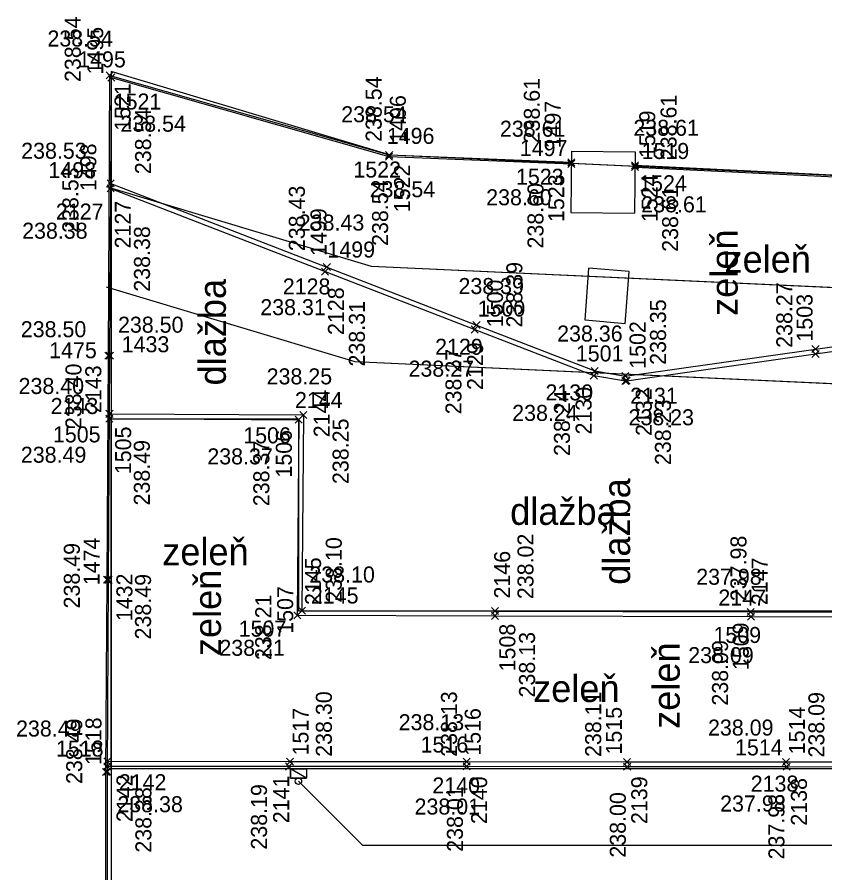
# Model space of a CAD drawing. Extents: x -264205 to -263659, y -1242401 to -1241986.
# Drawn here: x -263962.4 to -263937.18, y -1242084.56 to -1242057.84 of the extents above; entities that cross this region are included whole.
import ezdxf

# ---------------------------------------------------------------- set-up
doc = ezdxf.new("R2010")
doc.units = 0
for name, color, linetype in [('BOD_CISLO_2-2', 7, 'Continuous'), ('BOD_CISLO_2-3', 7, 'Continuous'), ('BOD_SYMBOL_2-2', 7, 'Continuous'), ('BOD_SYMBOL_2-3', 7, 'Continuous'), ('BOD_VYSKA_2-2', 7, 'Continuous'), ('BOD_VYSKA_2-3', 7, 'Continuous'), ('KFA_JESTVUJUCE_SACHTY', 7, 'Continuous'), ('POPIS_2-2', 7, 'Continuous'), ('POPIS_2-3', 7, 'Continuous'), ('PROJEKT_OBRUBNIKY_KOMUNIKACIE', 7, 'Continuous'), ('SITUACIA_DSP_2D', 7, 'Continuous'), ('SO_20-4_OBRUBNIKY_DOLNA_HRANA', 7, 'Continuous'), ('SO_20-4_OBRUBNIKY_HORNA_HRANA', 7, 'Continuous')]:
    doc.layers.add(name, color=color, linetype=linetype)

msp = doc.modelspace()

# ---------------------------------------------------------------- linework, layer by layer
at = {"layer": 'BOD_SYMBOL_2-2'}
for p, q in [((-263959.62, -1242059.771), (-263959.399, -1242059.549)), ((-263959.399, -1242059.771), (-263959.62, -1242059.549)), ((-263959.569, -1242059.836), (-263959.349, -1242059.616)), ((-263959.349, -1242059.836), (-263959.569, -1242059.616)), ((-263950.903, -1242062.306), (-263950.682, -1242062.085)), ((-263950.682, -1242062.306), (-263950.903, -1242062.085)), ((-263950.894, -1242062.255), (-263950.674, -1242062.035)), ((-263950.674, -1242062.255), (-263950.894, -1242062.035)), ((-263945.205, -1242062.482), (-263944.985, -1242062.262)), ((-263944.985, -1242062.482), (-263945.205, -1242062.262)), ((-263945.205, -1242062.532), (-263944.985, -1242062.312)), ((-263944.985, -1242062.532), (-263945.205, -1242062.312)), ((-263943.215, -1242062.579), (-263942.995, -1242062.357)), ((-263942.995, -1242062.579), (-263943.215, -1242062.357)), ((-263943.215, -1242062.633), (-263942.995, -1242062.413)), ((-263942.995, -1242062.633), (-263943.215, -1242062.413)), ((-263959.588, -1242063.144), (-263959.367, -1242062.924)), ((-263959.367, -1242063.144), (-263959.588, -1242062.924)), ((-263959.589, -1242063.299), (-263959.367, -1242063.079)), ((-263959.367, -1242063.299), (-263959.589, -1242063.079)), ((-263952.895, -1242065.894), (-263952.675, -1242065.674)), ((-263952.675, -1242065.894), (-263952.895, -1242065.674)), ((-263952.84, -1242065.755), (-263952.618, -1242065.535)), ((-263952.618, -1242065.755), (-263952.84, -1242065.535)), ((-263948.22, -1242067.704), (-263948, -1242067.482)), ((-263948, -1242067.704), (-263948.22, -1242067.482)), ((-263948.167, -1242067.568), (-263947.947, -1242067.346)), ((-263947.947, -1242067.568), (-263948.167, -1242067.346)), ((-263959.664, -1242068.525), (-263959.443, -1242068.303)), ((-263959.443, -1242068.525), (-263959.664, -1242068.303)), ((-263959.617, -1242068.525), (-263959.395, -1242068.303)), ((-263959.395, -1242068.525), (-263959.617, -1242068.303)), ((-263937.583, -1242068.465), (-263937.361, -1242068.245)), ((-263937.361, -1242068.465), (-263937.583, -1242068.245)), ((-263937.582, -1242068.316), (-263937.361, -1242068.096)), ((-263937.361, -1242068.316), (-263937.582, -1242068.096)), ((-263944.476, -1242068.998), (-263944.256, -1242068.776)), ((-263944.256, -1242068.998), (-263944.476, -1242068.776)), ((-263944.503, -1242069.144), (-263944.283, -1242068.923)), ((-263944.283, -1242069.144), (-263944.503, -1242068.923)), ((-263943.52, -1242069.16), (-263943.3, -1242068.94)), ((-263943.3, -1242069.16), (-263943.52, -1242068.94)), ((-263943.518, -1242069.309), (-263943.296, -1242069.088)), ((-263943.296, -1242069.309), (-263943.518, -1242069.088)), ((-263943.481, -1242069.306), (-263943.261, -1242069.085)), ((-263943.261, -1242069.306), (-263943.481, -1242069.085)), ((-263959.628, -1242070.339), (-263959.406, -1242070.117)), ((-263959.406, -1242070.339), (-263959.628, -1242070.117)), ((-263953.573, -1242070.372), (-263953.351, -1242070.15)), ((-263953.351, -1242070.372), (-263953.573, -1242070.15)), ((-263959.628, -1242070.488), (-263959.408, -1242070.266)), ((-263959.408, -1242070.488), (-263959.628, -1242070.266)), ((-263953.72, -1242070.521), (-263953.498, -1242070.299)), ((-263953.498, -1242070.521), (-263953.72, -1242070.299)), ((-263959.704, -1242075.516), (-263959.484, -1242075.296)), ((-263959.484, -1242075.516), (-263959.704, -1242075.296)), ((-263959.659, -1242075.521), (-263959.438, -1242075.299)), ((-263959.438, -1242075.521), (-263959.659, -1242075.299)), ((-263953.62, -1242076.478), (-263953.399, -1242076.258)), ((-263953.399, -1242076.478), (-263953.62, -1242076.258)), ((-263947.59, -1242076.494), (-263947.37, -1242076.272)), ((-263947.37, -1242076.494), (-263947.59, -1242076.272)), ((-263939.603, -1242076.522), (-263939.382, -1242076.302)), ((-263939.382, -1242076.522), (-263939.603, -1242076.302)), ((-263953.764, -1242076.626), (-263953.542, -1242076.404)), ((-263953.542, -1242076.626), (-263953.764, -1242076.404)), ((-263947.59, -1242076.644), (-263947.368, -1242076.424)), ((-263947.368, -1242076.644), (-263947.59, -1242076.424)), ((-263939.593, -1242076.668), (-263939.372, -1242076.448)), ((-263939.372, -1242076.668), (-263939.593, -1242076.448)), ((-263959.692, -1242081.343), (-263959.47, -1242081.123)), ((-263959.47, -1242081.343), (-263959.692, -1242081.123)), ((-263959.691, -1242081.194), (-263959.47, -1242080.972)), ((-263959.47, -1242081.194), (-263959.691, -1242080.972)), ((-263954.023, -1242081.349), (-263953.802, -1242081.127)), ((-263953.802, -1242081.349), (-263954.023, -1242081.127)), ((-263953.991, -1242081.201), (-263953.769, -1242080.981)), ((-263953.769, -1242081.201), (-263953.991, -1242080.981)), ((-263948.474, -1242081.2), (-263948.253, -1242080.978)), ((-263948.253, -1242081.2), (-263948.474, -1242080.978)), ((-263948.471, -1242081.345), (-263948.251, -1242081.123)), ((-263948.251, -1242081.345), (-263948.471, -1242081.123)), ((-263943.471, -1242081.208), (-263943.251, -1242080.988)), ((-263943.251, -1242081.208), (-263943.471, -1242080.988)), ((-263943.463, -1242081.353), (-263943.242, -1242081.133)), ((-263943.242, -1242081.353), (-263943.463, -1242081.133)), ((-263938.503, -1242081.211), (-263938.281, -1242080.99)), ((-263938.281, -1242081.211), (-263938.503, -1242080.99)), ((-263938.485, -1242081.357), (-263938.264, -1242081.137)), ((-263938.264, -1242081.357), (-263938.485, -1242081.137)), ((-263959.737, -1242081.516), (-263959.517, -1242081.296)), ((-263959.517, -1242081.516), (-263959.737, -1242081.296)), ((-263959.693, -1242081.512), (-263959.471, -1242081.292)), ((-263959.471, -1242081.512), (-263959.693, -1242081.292))]:
    msp.add_line(p, q, dxfattribs=at)
at = {"layer": 'BOD_SYMBOL_2-3'}
for p, q in [((-263959.399, -1242059.771), (-263959.62, -1242059.549)), ((-263959.399, -1242059.549), (-263959.62, -1242059.771)), ((-263959.349, -1242059.836), (-263959.569, -1242059.616)), ((-263959.349, -1242059.616), (-263959.569, -1242059.836)), ((-263950.682, -1242062.306), (-263950.903, -1242062.085)), ((-263950.682, -1242062.085), (-263950.903, -1242062.306)), ((-263950.674, -1242062.255), (-263950.894, -1242062.035)), ((-263950.674, -1242062.035), (-263950.894, -1242062.255)), ((-263944.985, -1242062.482), (-263945.205, -1242062.262)), ((-263944.985, -1242062.262), (-263945.205, -1242062.482)), ((-263944.985, -1242062.532), (-263945.205, -1242062.312)), ((-263944.985, -1242062.312), (-263945.205, -1242062.532)), ((-263942.995, -1242062.579), (-263943.215, -1242062.357)), ((-263942.995, -1242062.357), (-263943.215, -1242062.579)), ((-263942.995, -1242062.633), (-263943.215, -1242062.413)), ((-263942.995, -1242062.413), (-263943.215, -1242062.633)), ((-263959.367, -1242063.144), (-263959.588, -1242062.924)), ((-263959.367, -1242062.924), (-263959.588, -1242063.144)), ((-263959.367, -1242063.299), (-263959.589, -1242063.079)), ((-263959.367, -1242063.079), (-263959.589, -1242063.299)), ((-263952.675, -1242065.894), (-263952.895, -1242065.674)), ((-263952.675, -1242065.674), (-263952.895, -1242065.894)), ((-263952.618, -1242065.755), (-263952.84, -1242065.535)), ((-263952.618, -1242065.535), (-263952.84, -1242065.755)), ((-263948, -1242067.704), (-263948.22, -1242067.482)), ((-263948, -1242067.482), (-263948.22, -1242067.704)), ((-263947.947, -1242067.568), (-263948.167, -1242067.346)), ((-263947.947, -1242067.346), (-263948.167, -1242067.568)), ((-263959.443, -1242068.525), (-263959.664, -1242068.303)), ((-263959.443, -1242068.303), (-263959.664, -1242068.525)), ((-263959.395, -1242068.525), (-263959.617, -1242068.303)), ((-263959.395, -1242068.303), (-263959.617, -1242068.525)), ((-263937.361, -1242068.465), (-263937.583, -1242068.245)), ((-263937.361, -1242068.245), (-263937.583, -1242068.465)), ((-263937.361, -1242068.316), (-263937.582, -1242068.096)), ((-263937.361, -1242068.096), (-263937.582, -1242068.316)), ((-263944.256, -1242068.998), (-263944.476, -1242068.776)), ((-263944.256, -1242068.776), (-263944.476, -1242068.998)), ((-263944.283, -1242069.144), (-263944.503, -1242068.923)), ((-263944.283, -1242068.923), (-263944.503, -1242069.144)), ((-263943.3, -1242069.16), (-263943.52, -1242068.94)), ((-263943.3, -1242068.94), (-263943.52, -1242069.16)), ((-263943.296, -1242069.309), (-263943.518, -1242069.088)), ((-263943.296, -1242069.088), (-263943.518, -1242069.309)), ((-263943.261, -1242069.306), (-263943.481, -1242069.085)), ((-263943.261, -1242069.085), (-263943.481, -1242069.306)), ((-263959.406, -1242070.339), (-263959.628, -1242070.117)), ((-263959.406, -1242070.117), (-263959.628, -1242070.339)), ((-263953.351, -1242070.372), (-263953.573, -1242070.15)), ((-263953.351, -1242070.15), (-263953.573, -1242070.372)), ((-263959.408, -1242070.488), (-263959.628, -1242070.266)), ((-263959.408, -1242070.266), (-263959.628, -1242070.488)), ((-263953.498, -1242070.521), (-263953.72, -1242070.299)), ((-263953.498, -1242070.299), (-263953.72, -1242070.521)), ((-263959.484, -1242075.516), (-263959.704, -1242075.296)), ((-263959.484, -1242075.296), (-263959.704, -1242075.516)), ((-263959.438, -1242075.521), (-263959.659, -1242075.299)), ((-263959.438, -1242075.299), (-263959.659, -1242075.521)), ((-263953.399, -1242076.478), (-263953.62, -1242076.258)), ((-263953.399, -1242076.258), (-263953.62, -1242076.478)), ((-263947.37, -1242076.494), (-263947.59, -1242076.272)), ((-263947.37, -1242076.272), (-263947.59, -1242076.494)), ((-263939.382, -1242076.522), (-263939.603, -1242076.302)), ((-263939.382, -1242076.302), (-263939.603, -1242076.522)), ((-263953.542, -1242076.626), (-263953.764, -1242076.404)), ((-263953.542, -1242076.404), (-263953.764, -1242076.626)), ((-263947.368, -1242076.644), (-263947.59, -1242076.424)), ((-263947.368, -1242076.424), (-263947.59, -1242076.644)), ((-263939.372, -1242076.668), (-263939.593, -1242076.448)), ((-263939.372, -1242076.448), (-263939.593, -1242076.668)), ((-263959.47, -1242081.343), (-263959.692, -1242081.123)), ((-263959.47, -1242081.123), (-263959.692, -1242081.343)), ((-263959.47, -1242081.194), (-263959.691, -1242080.972)), ((-263959.47, -1242080.972), (-263959.691, -1242081.194)), ((-263953.802, -1242081.349), (-263954.023, -1242081.127)), ((-263953.802, -1242081.127), (-263954.023, -1242081.349)), ((-263953.769, -1242081.201), (-263953.991, -1242080.981)), ((-263953.769, -1242080.981), (-263953.991, -1242081.201)), ((-263948.253, -1242081.2), (-263948.474, -1242080.978)), ((-263948.253, -1242080.978), (-263948.474, -1242081.2)), ((-263948.251, -1242081.345), (-263948.471, -1242081.123)), ((-263948.251, -1242081.123), (-263948.471, -1242081.345)), ((-263943.251, -1242081.208), (-263943.471, -1242080.988)), ((-263943.251, -1242080.988), (-263943.471, -1242081.208)), ((-263943.242, -1242081.353), (-263943.463, -1242081.133)), ((-263943.242, -1242081.133), (-263943.463, -1242081.353)), ((-263938.281, -1242081.211), (-263938.503, -1242080.99)), ((-263938.281, -1242080.99), (-263938.503, -1242081.211)), ((-263938.264, -1242081.357), (-263938.485, -1242081.137)), ((-263938.264, -1242081.137), (-263938.485, -1242081.357)), ((-263959.517, -1242081.516), (-263959.737, -1242081.296)), ((-263959.517, -1242081.296), (-263959.737, -1242081.516)), ((-263959.471, -1242081.512), (-263959.693, -1242081.292)), ((-263959.471, -1242081.292), (-263959.693, -1242081.512))]:
    msp.add_line(p, q, dxfattribs=at)
at = {"layer": 'KFA_JESTVUJUCE_SACHTY'}
for p, q in [((-263945.09, -1242062.026), (-263945.116, -1242063.94)), ((-263944.666, -1242067.305), (-263944.545, -1242065.681))]:
    msp.add_line(p, q, dxfattribs=at)
for points in [[(-263945.09, -1242062.026), (-263943.099, -1242062.048), (-263943.125, -1242063.962)], [(-263945.116, -1242063.94), (-263943.125, -1242063.962)], [(-263943.411, -1242067.412), (-263943.29, -1242065.788), (-263944.545, -1242065.681)], [(-263943.411, -1242067.412), (-263944.666, -1242067.305)]]:
    msp.add_lwpolyline(points, dxfattribs=at)
at = {"layer": 'PROJEKT_OBRUBNIKY_KOMUNIKACIE'}
for p, q in [((-263950.745, -1242062.149), (-263959.468, -1242059.534)), ((-263959.468, -1242059.534), (-263959.468, -1242179.482)), ((-263926.771, -1242063.254), (-263950.745, -1242062.149)), ((-263959.468, -1242071.382), (-263959.468, -1242070.382)), ((-263959.468, -1242070.382), (-263953.617, -1242070.382)), ((-263953.617, -1242070.382), (-263953.617, -1242076.382)), ((-263959.468, -1242076.382), (-263959.468, -1242071.382)), ((-263959.468, -1242081.307), (-263959.468, -1242076.382)), ((-263953.617, -1242076.382), (-263929.58, -1242076.382)), ((-263953.617, -1242081.307), (-263959.468, -1242081.307)), ((-263929.58, -1242081.307), (-263953.617, -1242081.307))]:
    msp.add_line(p, q, dxfattribs=at)
for points in [[(-263863.949, -1242065.106), (-263895.455, -1242062.322), (-263915.197, -1242060.921), (-263926.771, -1242063.254), (-263950.745, -1242062.149), (-263959.468, -1242059.534)], [(-263864.257, -1242068.593), (-263895.733, -1242065.811), (-263914.971, -1242064.445), (-263926.501, -1242066.77), (-263951.337, -1242065.625), (-263959.611, -1242063.145)], [(-263864.521, -1242071.581), (-263895.971, -1242068.802), (-263914.777, -1242067.467), (-263926.271, -1242069.784), (-263951.845, -1242068.605), (-263959.611, -1242066.277)]]:
    msp.add_lwpolyline(points, dxfattribs=at)
at = {"layer": 'SITUACIA_DSP_2D'}
for p, q in [((-263959.468, -1242059.534), (-263959.468, -1242179.482)), ((-263950.745, -1242062.149), (-263959.468, -1242059.534)), ((-263950.745, -1242062.149), (-263959.468, -1242059.534)), ((-263926.771, -1242063.254), (-263950.745, -1242062.149)), ((-263926.771, -1242063.254), (-263950.745, -1242062.149)), ((-263951.337, -1242065.625), (-263959.611, -1242063.145)), ((-263926.501, -1242066.77), (-263951.337, -1242065.625)), ((-263951.845, -1242068.605), (-263959.611, -1242066.277)), ((-263926.271, -1242069.784), (-263951.845, -1242068.605)), ((-263959.468, -1242071.382), (-263959.468, -1242070.382)), ((-263959.468, -1242070.382), (-263953.617, -1242070.382)), ((-263953.617, -1242070.382), (-263953.617, -1242076.382)), ((-263959.468, -1242076.382), (-263959.468, -1242071.382)), ((-263959.468, -1242081.307), (-263959.468, -1242076.382)), ((-263953.617, -1242076.382), (-263929.58, -1242076.382)), ((-263953.617, -1242081.307), (-263959.468, -1242081.307)), ((-263953.868, -1242081.597), (-263953.868, -1242081.307)), ((-263953.868, -1242081.307), (-263953.368, -1242081.307)), ((-263953.368, -1242081.597), (-263953.868, -1242081.307)), ((-263953.368, -1242081.597), (-263953.868, -1242081.307)), ((-263953.868, -1242081.307), (-263953.868, -1242081.597)), ((-263929.58, -1242081.307), (-263953.617, -1242081.307)), ((-263953.368, -1242081.307), (-263953.368, -1242081.597)), ((-263953.368, -1242081.597), (-263953.868, -1242081.597)), ((-263953.868, -1242081.597), (-263953.368, -1242081.597)), ((-263953.618, -1242081.697), (-263951.618, -1242083.697)), ((-263953.547, -1242081.768), (-263951.618, -1242083.697)), ((-263951.618, -1242083.697), (-263918.806, -1242083.697))]:
    msp.add_line(p, q, dxfattribs=at)
msp.add_circle((-263953.618, -1242081.697), 0.1, dxfattribs=at)
at = {"layer": 'SO_20-4_OBRUBNIKY_DOLNA_HRANA'}
msp.add_line((-263959.517, -1242070.228), (-263953.462, -1242070.261), dxfattribs=at)
for points in [[(-263959.478, -1242063.189), (-263952.785, -1242065.784), (-263948.11, -1242067.593), (-263944.393, -1242069.033), (-263943.407, -1242069.198), (-263943.371, -1242069.195), (-263937.472, -1242068.355), (-263932.521, -1242067.649), (-263926.563, -1242066.793)], [(-263953.462, -1242070.261), (-263953.509, -1242076.368), (-263947.48, -1242076.383), (-263939.492, -1242076.412), (-263933.989, -1242076.423), (-263929.589, -1242076.427)], [(-263929.589, -1242076.427), (-263929.578, -1242081.252), (-263933.379, -1242081.255), (-263938.374, -1242081.247), (-263943.352, -1242081.243), (-263948.361, -1242081.234), (-263953.912, -1242081.238), (-263959.581, -1242081.233)]]:
    msp.add_lwpolyline(points, dxfattribs=at)
at = {"layer": 'SO_20-4_OBRUBNIKY_HORNA_HRANA'}
for points in [[(-263959.553, -1242068.414), (-263959.509, -1242059.66), (-263950.784, -1242062.145), (-263945.095, -1242062.372)], [(-263959.506, -1242068.414), (-263959.459, -1242059.726), (-263950.792, -1242062.195), (-263945.095, -1242062.422)], [(-263943.105, -1242062.468), (-263926.74, -1242063.264), (-263925.759, -1242063.066)], [(-263943.105, -1242062.523), (-263926.736, -1242063.319), (-263925.75, -1242063.112)], [(-263959.477, -1242063.034), (-263952.729, -1242065.645), (-263948.057, -1242067.457), (-263944.366, -1242068.887), (-263943.41, -1242069.05), (-263937.471, -1242068.206), (-263932.54, -1242067.502), (-263926.593, -1242066.647)], [(-263959.578, -1242123.367), (-263959.586, -1242113.378), (-263959.596, -1242106.383), (-263959.596, -1242100.388), (-263959.604, -1242094.394), (-263959.616, -1242088.401), (-263959.627, -1242081.406), (-263959.594, -1242075.406), (-263959.553, -1242068.414)], [(-263959.532, -1242123.37), (-263959.539, -1242113.376), (-263959.549, -1242106.383), (-263959.55, -1242100.394), (-263959.558, -1242094.392), (-263959.569, -1242088.4), (-263959.582, -1242081.402), (-263959.548, -1242075.41), (-263959.506, -1242068.414)], [(-263959.518, -1242070.377), (-263953.609, -1242070.41), (-263953.653, -1242076.515), (-263947.479, -1242076.534), (-263939.482, -1242076.558), (-263933.988, -1242076.571), (-263929.732, -1242076.573), (-263929.722, -1242081.108), (-263933.382, -1242081.107), (-263938.392, -1242081.1), (-263943.361, -1242081.098), (-263948.363, -1242081.089), (-263953.88, -1242081.091), (-263959.58, -1242081.083)]]:
    msp.add_lwpolyline(points, dxfattribs=at)

# ---------------------------------------------------------------- texts
at = {"layer": 'BOD_CISLO_2-2'}
for s, p in [('1495', (-263960.495, -1242059.41)), ('1521', (-263959.386, -1242060.726)), ('1496', (-263950.857, -1242061.799)), ('1497', (-263946.704, -1242062.179)), ('1519', (-263942.902, -1242062.271)), ('1498', (-263961.424, -1242062.869)), ('1522', (-263951.902, -1242062.85)), ('1523', (-263946.824, -1242063.075)), ('1524', (-263942.977, -1242063.279)), ('2127', (-263961.191, -1242064.161)), ('1499', (-263952.711, -1242065.348)), ('2128', (-263954.106, -1242066.5)), ('1500', (-263948.021, -1242067.189)), ('1433', (-263959.136, -1242068.305)), ('1475', (-263961.401, -1242068.491)), ('2129', (-263949.349, -1242068.383)), ('1501', (-263944.954, -1242068.59)), ('2130', (-263945.903, -1242069.808)), ('2131', (-263943.259, -1242069.912)), ('2144', (-263953.726, -1242070.046)), ('2143', (-263961.355, -1242070.233)), ('1505', (-263961.283, -1242071.119)), ('1506', (-263955.34, -1242071.148)), ('2145', (-263953.227, -1242076.149)), ('2147', (-263940.503, -1242076.213)), ('1507', (-263955.484, -1242077.184)), ('1509', (-263940.657, -1242077.381)), ('1516', (-263949.803, -1242080.802)), ('1518', (-263961.189, -1242080.927)), ('1514', (-263939.985, -1242080.892)), ('2142', (-263959.227, -1242081.978)), ('2140', (-263949.436, -1242082.079)), ('2138', (-263939.493, -1242082.022))]:
    msp.add_text(s, height=0.5, dxfattribs=at).set_placement(p)
at = {"layer": 'BOD_CISLO_2-3'}
for s, p in [('1495', (-263959.714, -1242059.634)), ('1521', (-263958.86, -1242061.392)), ('1496', (-263950.263, -1242061.765)), ('1497', (-263945.427, -1242061.94)), ('1519', (-263942.475, -1242062.244)), ('1498', (-263959.929, -1242063.274)), ('1522', (-263950.131, -1242063.935)), ('1523', (-263945.318, -1242064.239)), ('1524', (-263942.401, -1242064.241)), ('2127', (-263958.851, -1242065.063)), ('1499', (-263952.74, -1242065.296)), ('1500', (-263947.229, -1242067.525)), ('2128', (-263952.196, -1242067.766)), ('1503', (-263937.562, -1242067.972)), ('1502', (-263942.777, -1242068.821)), ('2129', (-263947.85, -1242069.483)), ('2143', (-263959.773, -1242070.202)), ('2130', (-263944.462, -1242070.871)), ('2144', (-263952.641, -1242070.959)), ('2132', (-263942.584, -1242070.918)), ('1505', (-263958.841, -1242072.111)), ('1506', (-263953.823, -1242072.217)), ('1474', (-263959.828, -1242075.578)), ('2145', (-263952.911, -1242076.196)), ('2146', (-263947.006, -1242075.993)), ('2147', (-263938.968, -1242076.199)), ('1432', (-263958.802, -1242076.701)), ('1507', (-263953.781, -1242077.093)), ('1508', (-263946.844, -1242078.268)), ('1509', (-263939.557, -1242078.229)), ('1517', (-263953.302, -1242080.893)), ('1516', (-263947.925, -1242080.902)), ('1515', (-263943.517, -1242080.864)), ('1514', (-263937.802, -1242080.855)), ('1518', (-263959.768, -1242081.193)), ('2142', (-263958.798, -1242082.973)), ('2141', (-263953.906, -1242083.008)), ('2140', (-263947.726, -1242083.035)), ('2139', (-263942.724, -1242083.034)), ('2138', (-263937.739, -1242083.085))]:
    msp.add_text(s, height=0.5, rotation=90, dxfattribs=at).set_placement(p)
at = {"layer": 'BOD_VYSKA_2-2'}
for s, p in [('238.54', (-263961.455, -1242058.759)), ('238.54', (-263952.28, -1242061.124)), ('238.54', (-263959.176, -1242061.419)), ('238.61', (-263947.325, -1242061.575)), ('238.61', (-263943.157, -1242061.547)), ('238.53', (-263962.275, -1242062.263)), ('238.54', (-263951.393, -1242063.464)), ('238.60', (-263947.754, -1242063.716)), ('238.61', (-263942.911, -1242063.936)), ('238.43', (-263953.606, -1242064.506)), ('238.38', (-263962.245, -1242064.76)), ('238.39', (-263948.619, -1242066.487)), ('238.31', (-263954.808, -1242067.147)), ('238.50', (-263959.251, -1242067.694)), ('238.50', (-263962.287, -1242067.835)), ('238.36', (-263945.538, -1242067.97)), ('238.27', (-263950.18, -1242069.067)), ('238.25', (-263954.61, -1242069.307)), ('238.40', (-263962.356, -1242069.608)), ('238.24', (-263946.942, -1242070.448)), ('238.23', (-263943.31, -1242070.585)), ('238.49', (-263962.285, -1242071.754)), ('238.37', (-263956.462, -1242071.805)), ('238.10', (-263953.275, -1242075.493)), ('237.98', (-263941.195, -1242075.564)), ('238.21', (-263956.086, -1242077.782)), ('238.09', (-263941.445, -1242078.01)), ('238.49', (-263962.435, -1242080.302)), ('238.13', (-263950.487, -1242080.105)), ('238.09', (-263940.827, -1242080.272)), ('238.38', (-263959.271, -1242082.665)), ('238.01', (-263949.991, -1242082.738)), ('237.98', (-263940.449, -1242082.643))]:
    msp.add_text(s, height=0.5, dxfattribs=at).set_placement(p)
at = {"layer": 'BOD_VYSKA_2-3'}
for s, p in [('238.54', (-263960.415, -1242059.867)), ('238.54', (-263951.018, -1242061.737)), ('238.61', (-263946.079, -1242061.785)), ('238.61', (-263941.808, -1242062.308)), ('238.54', (-263958.219, -1242062.745)), ('238.53', (-263960.488, -1242064.577)), ('238.54', (-263950.818, -1242064.985)), ('238.43', (-263953.417, -1242065.149)), ('238.60', (-263945.965, -1242065.066)), ('238.61', (-263941.761, -1242065.169)), ('238.38', (-263958.252, -1242066.414)), ('238.39', (-263946.625, -1242067.531)), ('238.27', (-263938.195, -1242068.168)), ('238.31', (-263951.542, -1242068.75)), ('238.35', (-263942.139, -1242068.698)), ('238.27', (-263948.526, -1242070.242)), ('238.40', (-263960.392, -1242070.703)), ('238.24', (-263945.139, -1242071.541)), ('238.23', (-263941.985, -1242071.826)), ('238.25', (-263952.05, -1242072.419)), ('238.49', (-263958.257, -1242073.088)), ('238.37', (-263954.526, -1242073.111)), ('238.10', (-263952.265, -1242076.124)), ('238.02', (-263946.277, -1242076.013)), ('237.98', (-263939.627, -1242076.076)), ('238.49', (-263960.443, -1242076.304)), ('238.49', (-263958.22, -1242077.271)), ('238.21', (-263954.466, -1242077.913)), ('238.13', (-263946.229, -1242079.083)), ('238.09', (-263940.202, -1242079.337)), ('238.30', (-263952.573, -1242080.935)), ('238.13', (-263948.665, -1242080.936)), ('238.11', (-263944.163, -1242080.941)), ('238.09', (-263937.194, -1242080.958)), ('238.49', (-263960.369, -1242081.784)), ('238.38', (-263958.209, -1242083.928)), ('238.19', (-263954.599, -1242083.833)), ('238.01', (-263948.481, -1242083.9)), ('238.00', (-263943.394, -1242084.084)), ('237.98', (-263938.442, -1242084.139))]:
    msp.add_text(s, height=0.5, rotation=90, dxfattribs=at).set_placement(p)
at = {"layer": 'POPIS_2-2'}
for s, p in [('zeleň', (-263940.312, -1242065.82)), ('dlažba', (-263947.005, -1242073.693)), ('zeleň', (-263957.869, -1242074.954)), ('zeleň', (-263946.288, -1242079.225))]:
    msp.add_text(s, height=0.8438, dxfattribs=at).set_placement(p)
at = {"layer": 'POPIS_2-3'}
for s, p in [('zeleň', (-263939.902, -1242067.17)), ('dlažba', (-263955.884, -1242069.341)), ('dlažba', (-263943.259, -1242075.564)), ('zeleň', (-263956.036, -1242077.791)), ('zeleň', (-263941.71, -1242080.062))]:
    msp.add_text(s, height=0.8438, rotation=90, dxfattribs=at).set_placement(p)

doc.saveas('drawing.dxf')
